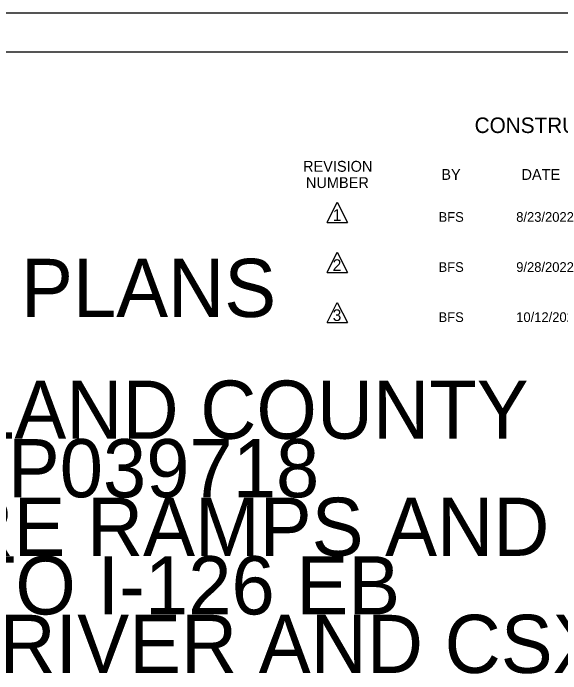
# Model space of a CAD drawing. Extents: x -1142 to 658, y -589 to 511.
# Drawn here: x -93 to 260.1, y 84.8 to 510.7 of the extents above; entities that cross this region are included whole.
import ezdxf

# ---------------------------------------------------------------- set-up
doc = ezdxf.new("R2010")
doc.units = 0
for name, color, linetype in [('BR_BORDER LINES', 7, 'Continuous'), ('BR_TEXT', 7, 'Continuous'), ('Default', 7, 'Continuous'), ('Level 31', 7, 'Continuous')]:
    doc.layers.add(name, color=color, linetype=linetype)

msp = doc.modelspace()

# ---------------------------------------------------------------- linework, layer by layer
at = {"layer": 'BR_BORDER LINES'}
msp.add_line((-1041.79, 485.67), (633.21, 485.67), dxfattribs=at)
at = {"layer": 'BR_TEXT'}
for p, q in [((109.45, 375.81), (115.95, 388.81)), ((115.95, 388.81), (122.45, 375.81)), ((109.45, 375.81), (122.45, 375.81)), ((109.45, 343.52), (115.95, 356.52)), ((115.95, 356.52), (122.45, 343.52)), ((109.45, 343.52), (122.45, 343.52)), ((109.45, 311.24), (115.95, 324.24)), ((115.95, 324.24), (122.45, 311.24)), ((109.45, 311.24), (122.45, 311.24))]:
    msp.add_line(p, q, dxfattribs=at)
at = {"layer": 'Level 31'}
msp.add_line((658.21, 510.67), (-1141.79, 510.67), dxfattribs=at)

# ---------------------------------------------------------------- texts
at = {"layer": 'BR_TEXT'}
for s, p in [('1', (112.98, 376.81)), ('2', (112.98, 344.52)), ('3', (112.98, 312.24))]:
    msp.add_text(s, height=7.5, dxfattribs=at).set_placement(p)
at = {"layer": 'Default'}
for s, height, p in [('CONSTRUCTION REVISIONS', 9.9999, (204.5, 433.43)), ('REVISION', 7, (93.87, 408.46)), ('BY', 7, (183.02, 403.21)), ('DATE', 7, (234.71, 403.21)), ('NUMBER', 7, (95.72, 397.96)), ('BFS', 6.25, (181.25, 376.19)), ('8/23/2022', 6.25, (231.31, 376.19)), ('PROPOSED PLANS', 37.5, (-386.08, 314.82)), ('BFS', 6.25, (181.25, 343.9)), ('9/28/2022', 6.25, (231.31, 343.9)), ('BFS', 6.25, (181.25, 311.61)), ('10/12/2022', 6.25, (231.31, 311.61)), ('LEXINGTON RICHLAND COUNTY', 37.5, (-546.4, 236.33)), ('PROJECT ID P039718', 37.5, (-408.5, 198.58)), ('I-26 TO I-20 FUTURE RAMPS AND ', 37.5, (-546.99, 160.83)), ('RAMP I-26 WB TO I-126 EB ', 37.5, (-476.12, 123.08)), ('BRIDGE OVER SALUDA RIVER AND CSX R.R.', 37.5, (-678.68, 85.33))]:
    msp.add_text(s, height=height, dxfattribs=at).set_placement(p)

doc.saveas('drawing.dxf')
